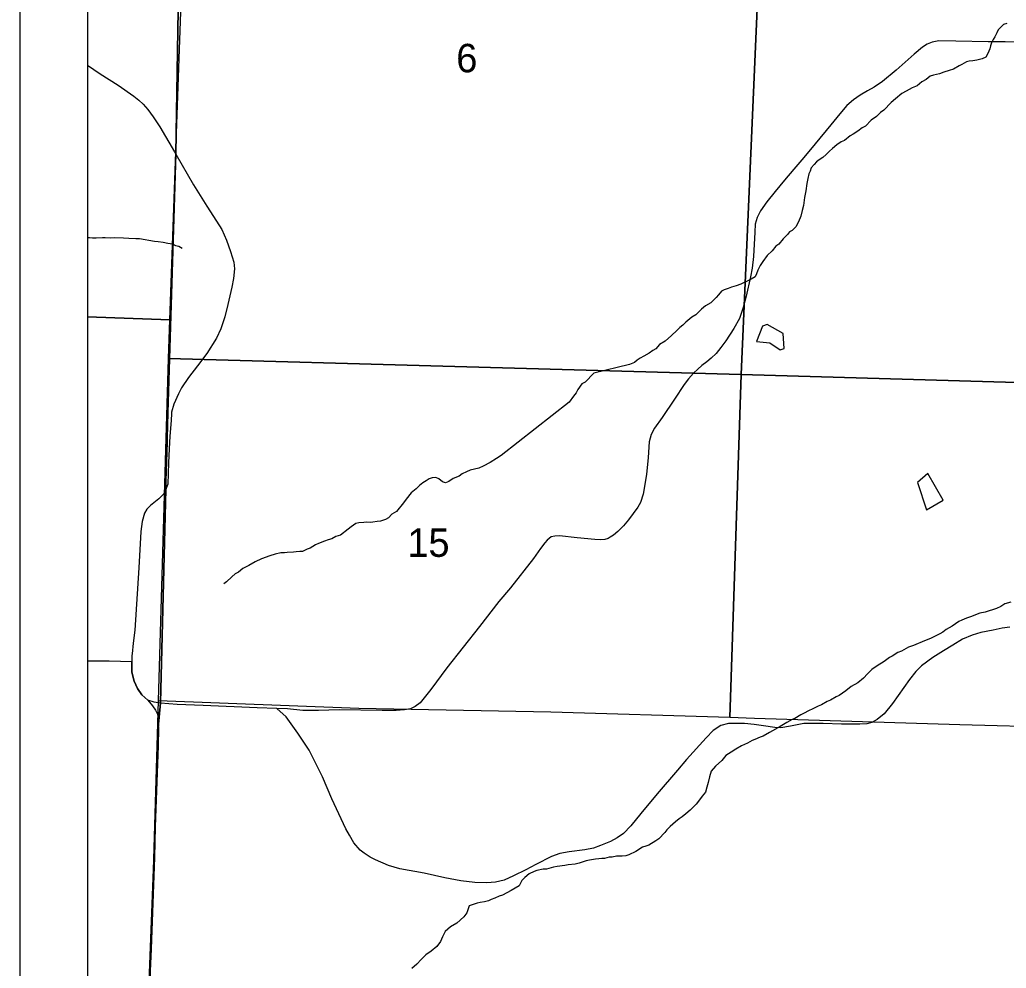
# Model space of a CAD drawing. Extents: x 0 to 34, y 0 to 22.
# Drawn here: x 2 to 3.454, y 18.529 to 19.927 of the extents above; entities that cross this region are included whole.
import ezdxf

# ---------------------------------------------------------------- set-up
doc = ezdxf.new("R2010")
doc.units = 0
for name, color, linetype in [('GM_X_Corporation', 7, 'Continuous'), ('GM_X_County_Road', 7, 'Continuous'), ('GM_X_Minor_Lake', 7, 'Continuous'), ('GM_X_Minor_River', 7, 'Continuous'), ('GM_X_Section_Text', 7, 'Continuous'), ('GM_X_Township_Road', 7, 'Continuous'), ('SH_Data', 7, 'Continuous')]:
    doc.layers.add(name, color=color, linetype=linetype)

msp = doc.modelspace()

# ---------------------------------------------------------------- linework, layer by layer
at = {"layer": 'GM_X_Corporation'}
for points in [[(8.9, 20.9), (2.1, 20.9), (2.1, 16.4477), (2.1182, 16.4474), (2.1176, 16.4327), (2.1175, 16.4298), (2.1166, 16.4244), (2.1155, 16.4201), (2.2605, 16.4147), (2.3623, 16.41), (2.7707, 16.392), (3.0057, 16.3809), (3.6165, 16.3686), (3.7537, 16.3728), (3.9899, 16.3631), (4.4958, 16.358), (4.9914, 16.3477), (5.6931, 16.3352)], [(2.1894, 18.4715), (2.1995, 18.7384), (2.2038, 18.8576), (2.2042, 18.8835), (2.2075, 18.9201), (2.2151, 19.2353), (2.2155, 19.2474), (2.2163, 19.2747), (2.2173, 19.3051), (2.2174, 19.3106), (2.2185, 19.3474), (2.2301, 19.7293), (2.2346, 20.0021), (2.2795, 20.9), (2.1, 20.9), (2.1, 16.4477)], [(7.1302, 20.9), (2.2795, 20.9), (2.2346, 20.0021), (2.2301, 19.7293), (2.2185, 19.3474), (2.2174, 19.3106), (2.2173, 19.3051), (2.2163, 19.2747), (2.2155, 19.2474), (2.2151, 19.2353), (2.2075, 18.9201), (2.2042, 18.8835), (2.2038, 18.8576), (2.1995, 18.7384), (2.1894, 18.4715)]]:
    msp.add_lwpolyline(points, dxfattribs=at)
for points in [[(2.1, 20.5146), (2.1, 19.4892), (2.2214, 19.4847), (2.2557, 20.4469), (2.2584, 20.5106)], [(3.1077, 20.4159), (3.063, 19.4039), (2.2194, 19.4275), (2.2214, 19.4847), (2.2557, 20.4469)], [(3.1077, 20.4159), (4.0987, 20.3855), (4.0627, 19.3751), (3.063, 19.4039)], [(2.1, 19.4892), (2.1, 18.4766), (2.1911, 18.4732), (2.2044, 18.9234), (2.2194, 19.4275), (2.2214, 19.4847)], [(2.2194, 19.4275), (3.063, 19.4039), (3.0465, 18.8987), (2.7828, 18.9065), (2.4998, 18.9122), (2.2044, 18.9234)], [(3.063, 19.4039), (4.0627, 19.3751), (4.0466, 18.8695), (3.9533, 18.8722), (3.6794, 18.8799), (3.3857, 18.8878), (3.0828, 18.8971), (3.0465, 18.8987)]]:
    msp.add_lwpolyline(points, close=True, dxfattribs=at)
at = {"layer": 'GM_X_County_Road'}
for points in [[(2.1, 19.8601), (2.1186, 19.847), (2.1449, 19.8304), (2.1683, 19.814), (2.1753, 19.8084), (2.1821, 19.8023), (2.1889, 19.7945), (2.1966, 19.7838), (2.2067, 19.769), (2.2283, 19.7322)], [(2.2283, 19.7322), (2.2303, 19.7288), (2.2563, 19.6838), (2.2757, 19.6521), (2.2899, 19.6302), (2.2979, 19.6178), (2.3045, 19.6019), (2.3107, 19.5852), (2.3154, 19.5695), (2.3163, 19.5596), (2.3152, 19.5458), (2.3125, 19.533), (2.3065, 19.5073), (2.3021, 19.4893), (2.2966, 19.4716), (2.2899, 19.4575), (2.2759, 19.4352), (2.2622, 19.4169), (2.2489, 19.3999), (2.2385, 19.3844), (2.2341, 19.3755), (2.2273, 19.3604), (2.2239, 19.3485), (2.2238, 19.3466)], [(2.2238, 19.3466), (2.2232, 19.3362), (2.2214, 19.3131), (2.2203, 19.2945), (2.2194, 19.2739), (2.2183, 19.2426), (2.2163, 19.2374)], [(2.2163, 19.2374), (2.2153, 19.2348), (2.212, 19.2278), (2.2051, 19.221), (2.1925, 19.2112), (2.1874, 19.2057), (2.1839, 19.1998), (2.1804, 19.1876), (2.1787, 19.1729), (2.1753, 19.1191), (2.1695, 19.0274), (2.167, 19.0082), (2.1657, 18.9925), (2.1654, 18.9899), (2.1652, 18.9808)], [(2.1652, 18.9808), (2.1654, 18.9656), (2.1685, 18.952), (2.1736, 18.9415), (2.1799, 18.932), (2.189, 18.924)], [(2.189, 18.924), (2.1959, 18.9161), (2.2003, 18.9096), (2.2029, 18.9034), (2.2038, 18.8957), (2.2041, 18.8888)], [(2.2041, 18.8888), (2.2044, 18.8829), (2.204, 18.8571), (2.1997, 18.7378), (2.1985, 18.6923), (2.1935, 18.5576), (2.1896, 18.471), (2.1886, 18.4108), (2.1881, 18.3566), (2.1875, 18.337), (2.1864, 18.3051), (2.1864, 18.2942), (2.1872, 18.2858), (2.1881, 18.2822)]]:
    msp.add_lwpolyline(points, dxfattribs=at)
at = {"layer": 'GM_X_Minor_Lake'}
for points in [[(3.1017, 19.478), (3.0949, 19.4753), (3.0859, 19.4526), (3.1056, 19.4507), (3.1208, 19.4405)], [(3.1208, 19.4405), (3.1268, 19.4424), (3.1253, 19.4644), (3.1017, 19.478)], [(3.3384, 19.2581), (3.3229, 19.2448), (3.3363, 19.2049)], [(3.3363, 19.2049), (3.3609, 19.219), (3.3384, 19.2581)]]:
    msp.add_lwpolyline(points, dxfattribs=at)
at = {"layer": 'GM_X_Minor_River'}
for points in [[(3.4547, 19.9215), (3.4498, 19.9196), (3.4422, 19.912), (3.44, 19.9074), (3.437, 19.9017), (3.4347, 19.8975), (3.4324, 19.893), (3.4309, 19.8884), (3.4298, 19.8842), (3.4268, 19.877), (3.4238, 19.8717), (3.4185, 19.8694), (3.4105, 19.8671), (3.4049, 19.8663), (3.3995, 19.866), (3.3954, 19.8648), (3.3886, 19.861), (3.3844, 19.8591), (3.3761, 19.8538), (3.3697, 19.8522), (3.3621, 19.8496), (3.3556, 19.8469), (3.3469, 19.845), (3.342, 19.8435), (3.336, 19.8389), (3.3295, 19.8351), (3.3227, 19.8294), (3.3152, 19.8263), (3.3065, 19.8214), (3.3, 19.818), (3.2906, 19.8104), (3.2842, 19.805), (3.2736, 19.7936), (3.2687, 19.7902), (3.2626, 19.7845), (3.2547, 19.7788), (3.2464, 19.7701), (3.2414, 19.7674), (3.235, 19.7625), (3.2282, 19.7583), (3.2237, 19.7556), (3.2154, 19.7491), (3.2104, 19.7468), (3.2044, 19.7423), (3.198, 19.737), (3.1934, 19.7332), (3.1885, 19.7282), (3.1836, 19.7237), (3.1783, 19.7206), (3.1741, 19.7176), (3.1707, 19.7134), (3.1666, 19.7084), (3.1651, 19.7035), (3.1628, 19.6997), (3.1613, 19.6929), (3.1602, 19.6853), (3.1584, 19.6747), (3.1565, 19.6648), (3.155, 19.653), (3.1531, 19.6458), (3.1513, 19.6375), (3.1475, 19.6291), (3.1437, 19.6219), (3.1384, 19.6162)], [(3.1384, 19.6162), (3.1343, 19.6143), (3.1313, 19.6105), (3.1252, 19.604), (3.1188, 19.596), (3.1143, 19.593), (3.109, 19.5862), (3.1014, 19.5793), (3.0954, 19.5706), (3.0912, 19.5645), (3.0878, 19.558), (3.086, 19.5523), (3.0841, 19.5482), (3.078, 19.5444), (3.0739, 19.5425), (3.0629, 19.5371), (3.0557, 19.5348), (3.0489, 19.5329), (3.0443, 19.531), (3.0383, 19.5287), (3.0341, 19.5268), (3.0296, 19.5215), (3.0262, 19.5177), (3.0186, 19.5097), (3.0107, 19.5052), (3.0046, 19.5006), (2.9963, 19.4922), (2.9907, 19.4888), (2.9816, 19.4812), (2.9774, 19.477), (2.9729, 19.4732), (2.9684, 19.469), (2.9604, 19.4618), (2.9514, 19.4534), (2.943, 19.4481), (2.9374, 19.4417), (2.9332, 19.4397), (2.9275, 19.4356), (2.92, 19.431), (2.9143, 19.428), (2.9101, 19.4253), (2.906, 19.4219), (2.8988, 19.4188), (2.8462, 19.4062), (2.8333, 19.3929), (2.8284, 19.3902), (2.8227, 19.3819), (2.8201, 19.3773), (2.8163, 19.372), (2.8099, 19.3632), (2.7097, 19.2849), (2.7029, 19.2803), (2.6935, 19.2746), (2.6829, 19.2689), (2.6764, 19.2659), (2.67, 19.2647), (2.6639, 19.2632), (2.6583, 19.2605), (2.6522, 19.2578), (2.6477, 19.2544), (2.639, 19.251), (2.6322, 19.2464), (2.6276, 19.2445), (2.6231, 19.246), (2.6177, 19.2506), (2.6132, 19.2521), (2.6079, 19.2517), (2.6033, 19.2502), (2.5988, 19.2475), (2.5943, 19.2444), (2.5894, 19.2406), (2.5844, 19.2357), (2.5769, 19.2296), (2.5697, 19.2205), (2.5656, 19.2152), (2.5554, 19.2023), (2.5486, 19.1984), (2.5436, 19.1931), (2.5391, 19.1905), (2.5315, 19.1882), (2.527, 19.1874), (2.5202, 19.1866), (2.5164, 19.1862), (2.5118, 19.1866), (2.5069, 19.1858), (2.4997, 19.1854), (2.4952, 19.1847), (2.4887, 19.1794), (2.4838, 19.1763), (2.4725, 19.1676), (2.466, 19.1653), (2.46, 19.1622), (2.4547, 19.1603), (2.449, 19.1584), (2.4403, 19.155), (2.4361, 19.1531), (2.4282, 19.1481), (2.4237, 19.1466), (2.4168, 19.1435), (2.4127, 19.1432), (2.4074, 19.1428)], [(2.1, 19.6058), (2.1029, 19.6058), (2.1074, 19.6054), (2.1127, 19.6054), (2.1222, 19.6058), (2.126, 19.6058), (2.1332, 19.6055)], [(2.1332, 19.6055), (2.14, 19.6059), (2.1529, 19.6055), (2.1608, 19.6051), (2.1711, 19.6044), (2.1764, 19.6044), (2.1847, 19.6029), (2.1904, 19.6022), (2.1987, 19.6007), (2.204, 19.5999), (2.2113, 19.5992), (2.2185, 19.5977), (2.2253, 19.5965), (2.2298, 19.5943), (2.2344, 19.5931), (2.2393, 19.5901)], [(2.4074, 19.1428), (2.4036, 19.1424), (2.3941, 19.1416), (2.3903, 19.1412), (2.3846, 19.1412), (2.3767, 19.1393), (2.3684, 19.137), (2.3562, 19.1324), (2.3468, 19.1282), (2.3377, 19.1225), (2.329, 19.1183), (2.3222, 19.113), (2.3173, 19.1103), (2.3127, 19.1058), (2.3048, 19.0986), (2.3007, 19.0955)], [(3.4606, 19.0686), (3.4519, 19.066), (3.4459, 19.0621), (3.4394, 19.0595), (3.4228, 19.0541)], [(3.4228, 19.0541), (3.4148, 19.0522), (3.4012, 19.0469), (3.3955, 19.045), (3.3883, 19.0419), (3.3838, 19.04), (3.374, 19.0332), (3.3698, 19.0309), (3.3653, 19.0282), (3.3604, 19.0244), (3.3558, 19.0221), (3.3422, 19.0149), (3.3335, 19.0119), (3.3172, 19.005), (3.31, 19.0023), (3.2994, 18.9966), (3.2941, 18.9947), (3.2858, 18.989), (3.2817, 18.9871), (3.2741, 18.9814), (3.2635, 18.9749), (3.2556, 18.9692), (3.2495, 18.9631), (3.2435, 18.9567), (3.2352, 18.9498), (3.2253, 18.9445), (3.2174, 18.938), (3.2076, 18.9312), (3.2034, 18.9293), (3.1947, 18.924), (3.1901, 18.9221), (3.1814, 18.9175), (3.1769, 18.9156), (3.1678, 18.911), (3.1633, 18.9091), (3.1553, 18.9045), (3.1512, 18.9026), (3.1425, 18.8973), (3.1383, 18.8958), (3.1304, 18.8912), (3.1205, 18.8855), (3.1096, 18.879), (3.105, 18.8767), (3.0959, 18.8714), (3.0914, 18.8699), (3.0835, 18.8661), (3.0793, 18.8646), (3.0725, 18.8611), (3.0638, 18.8569), (3.0555, 18.852), (3.0487, 18.8478), (3.0407, 18.8425), (3.0347, 18.8353), (3.0256, 18.8269), (3.0192, 18.8197), (3.0166, 18.8113), (3.0147, 18.803), (3.0128, 18.7961), (3.0106, 18.7889), (3.006, 18.7828), (3.0019, 18.7775), (2.997, 18.7711), (2.9879, 18.762), (2.9819, 18.7566), (2.9762, 18.7524), (2.9717, 18.7494), (2.9667, 18.7452), (2.9626, 18.7414), (2.9584, 18.738), (2.9539, 18.7331), (2.9509, 18.7293), (2.9418, 18.7198), (2.9373, 18.7171), (2.9274, 18.7106), (2.9229, 18.7091), (2.918, 18.7076), (2.9078, 18.7011), (2.8979, 18.6965), (2.8934, 18.695), (2.8881, 18.6942), (2.8835, 18.6942), (2.8797, 18.6946), (2.8729, 18.6931), (2.8688, 18.6927), (2.8616, 18.6911), (2.8578, 18.6908), (2.8536, 18.6904), (2.8487, 18.69), (2.8396, 18.6884), (2.8347, 18.6873), (2.8244, 18.6839), (2.8184, 18.6827), (2.8085, 18.6816), (2.8032, 18.6804), (2.7919, 18.6792), (2.7866, 18.6781), (2.7763, 18.6754), (2.7714, 18.675), (2.7623, 18.6731), (2.7582, 18.672), (2.751, 18.6682)], [(2.751, 18.6682), (2.7442, 18.6628), (2.74, 18.6583), (2.7363, 18.6507), (2.7245, 18.6438), (2.7117, 18.637), (2.7067, 18.6355), (2.7003, 18.6324), (2.695, 18.6305), (2.6909, 18.6286), (2.6848, 18.6271), (2.6784, 18.6259), (2.6742, 18.6251), (2.6666, 18.6225), (2.6625, 18.621), (2.6587, 18.6111), (2.6545, 18.605), (2.6443, 18.5955), (2.6349, 18.5902), (2.627, 18.5833), (2.6232, 18.5757), (2.6202, 18.5685), (2.6145, 18.5613), (2.6062, 18.5545), (2.5983, 18.5488), (2.5918, 18.5423), (2.5854, 18.5351), (2.5779, 18.529)]]:
    msp.add_lwpolyline(points, dxfattribs=at)
at = {"layer": 'GM_X_Township_Road'}
for points in [[(3.5086, 19.8926), (3.4525, 19.8942), (3.4273, 19.8944), (3.3796, 19.8954), (3.3547, 19.8958), (3.3447, 19.8938), (3.3373, 19.8909), (3.3305, 19.8866), (3.3182, 19.8761), (3.2915, 19.8527), (3.2713, 19.8357), (3.2592, 19.8274), (3.2496, 19.8223), (3.2385, 19.8157), (3.2286, 19.809), (3.219, 19.8003), (3.2085, 19.7882), (3.1953, 19.772), (3.1723, 19.7438), (3.1555, 19.7237), (3.1409, 19.7066), (3.1269, 19.6904), (3.1134, 19.6736), (3.1011, 19.6584), (3.0916, 19.6454), (3.0869, 19.6356), (3.084, 19.6255), (3.0832, 19.6136), (3.0815, 19.5779), (3.0795, 19.5606), (3.077, 19.5481), (3.0704, 19.5193), (3.0661, 19.5027), (3.0606, 19.4864), (3.0522, 19.4717), (3.0407, 19.4538), (3.0333, 19.4439), (3.0263, 19.4349), (3.0189, 19.4283), (3.0125, 19.4226), (3.0053, 19.4174), (2.9992, 19.4121), (2.993, 19.4059), (2.9856, 19.3977), (2.979, 19.3893), (2.9649, 19.3677), (2.9468, 19.3408), (2.9353, 19.325), (2.9308, 19.3155), (2.9279, 19.3051), (2.926, 19.2818), (2.9236, 19.2568), (2.9188, 19.228), (2.9147, 19.2155), (2.9108, 19.2085), (2.9041, 19.1993), (2.8971, 19.1898), (2.8897, 19.181), (2.8815, 19.1726), (2.8749, 19.1674), (2.8702, 19.1643), (2.8671, 19.1623), (2.8622, 19.1609), (2.8558, 19.1607), (2.8474, 19.1609), (2.8215, 19.1633), (2.7954, 19.1664), (2.7888, 19.166), (2.7833, 19.1648), (2.7775, 19.1602), (2.774, 19.1561), (2.7677, 19.1475), (2.7572, 19.1331), (2.7231, 19.0898), (2.7062, 19.0696), (2.6775, 19.0329), (2.6294, 18.9719), (2.606, 18.9398), (2.5902, 18.9205), (2.583, 18.915), (2.576, 18.9117), (2.5672, 18.91), (2.5546, 18.9088), (2.5341, 18.9088), (2.4708, 18.9102), (2.4402, 18.9092), (2.4174, 18.909), (2.3944, 18.9113), (2.379, 18.9118), (2.35, 18.9131), (2.2704, 18.9164), (2.2321, 18.918), (2.2077, 18.9196), (2.1983, 18.9211), (2.189, 18.924)], [(3.4593, 19.032), (3.448, 19.0301), (3.4347, 19.0276), (3.4164, 19.0239), (3.4035, 19.0201), (3.3896, 19.0139), (3.3754, 19.0055), (3.3612, 18.9969), (3.3458, 18.987), (3.3292, 18.9747), (3.3206, 18.9667), (3.3114, 18.9548), (3.2863, 18.9195), (3.2738, 18.9043), (3.2639, 18.8957), (3.256, 18.8912), (3.2485, 18.8893), (3.2383, 18.8889), (3.211, 18.8889), (3.1841, 18.8897), (3.1673, 18.8901), (3.1554, 18.8897), (3.1361, 18.886), (3.1215, 18.8836), (3.1129, 18.8838), (3.0962, 18.8864), (3.0823, 18.8885), (3.0681, 18.8897), (3.0544, 18.8901), (3.0447, 18.8897), (3.0334, 18.8868), (3.0221, 18.8794), (3.0115, 18.8689), (2.9829, 18.837), (2.9694, 18.8212), (2.9396, 18.7863), (2.9154, 18.7573), (2.9008, 18.7391), (2.89, 18.728), (2.8807, 18.7212), (2.8707, 18.7161), (2.8559, 18.7099), (2.8454, 18.7064), (2.833, 18.7037), (2.8099, 18.7007), (2.7958, 18.6982), (2.7838, 18.6939), (2.7607, 18.682), (2.7457, 18.6742), (2.7278, 18.6654), (2.7141, 18.6588), (2.7013, 18.6559), (2.6884, 18.6549), (2.6708, 18.6555), (2.6502, 18.658), (2.6264, 18.6625), (2.596, 18.6691), (2.5603, 18.6758), (2.5435, 18.6806), (2.5242, 18.689), (2.5164, 18.6927), (2.5078, 18.6986), (2.5019, 18.7032), (2.4924, 18.714), (2.4858, 18.7253), (2.4805, 18.7348), (2.4598, 18.7787), (2.4464, 18.8111), (2.4316, 18.8407), (2.4267, 18.8507), (2.4099, 18.8756), (2.3929, 18.8999), (2.379, 18.9118)], [(2.1652, 18.9808), (2.1318, 18.9815), (2.1, 18.9818)], [(2.189, 18.924), (2.1799, 18.932), (2.1736, 18.9415), (2.1685, 18.952), (2.1654, 18.9656), (2.1652, 18.9808)]]:
    msp.add_lwpolyline(points, dxfattribs=at)
at = {"layer": 'SH_Data'}
for p, q in [((2, 21), (2, 14)), ((2.1, 20.9), (2.1, 14.1))]:
    msp.add_line(p, q, dxfattribs=at)

# ---------------------------------------------------------------- texts
at = {"layer": 'GM_X_Section_Text'}
for s, height, p in [('6', 0.0419, (2.6433, 19.8494)), ('15', 0.04186, (2.5712, 19.1354))]:
    msp.add_text(s, height=height, rotation=0, dxfattribs=at).set_placement(p)

doc.saveas('drawing.dxf')
